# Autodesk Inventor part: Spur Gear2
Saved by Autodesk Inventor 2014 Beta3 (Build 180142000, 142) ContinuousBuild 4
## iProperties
Created: 2011-01
Part Number: Spur Gear2
Material: Steel
Document SubType Name: Modeling
Designer: Beta-8540w
Categories: <?xml version="1.0" encoding="UTF-16"?> <MemberInstance><Categories><FamilyTemplate><FamilyTemplateParameter ValueType="xs:double" Id="1" ObjectReferenceKey="da
Density: 1 g/cm^3
Appearance: Steel
CustomPartVersion: 1
Author: Beta-8540w
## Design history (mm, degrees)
sketch "Sketch1"
  geometry: C1 r 40.8 at (0, 0)
  constraints: 1 centre point
  dimensions: "d0" = 81.6 diameter of C1 (= da_da)
extrude "Extrusion1" new body sketch "Sketch1" distance "d1" = 13 (= da_b); taper "d2" = 0 deg
workplane "Work Plane2"
sketch "Sketch2"
  geometry: C1 r 40.8 at (0, 0) reference; C2 r 40 at (0, 0)
  constraints: 1 centre point, 1 coincident
  dimensions: "d3" = 80 diameter of C2 (= da_dw)
feature "Pitch Diameter" sketch "Sketch2" dims "d4" = 10, "d5" = 0
workplane "Work Plane8"
workplane "Work Plane9"
feature "Spur Gear" dims "da_b" = 13, "da_d" = 80, "da_aw" = 50, "da_da" = 81.6, "da_df" = 78, "da_dw" = 80, angle "da_beta" = 0 deg, "da_lefttooth" = 0, "da_righttooth" = 0
body "Solid1"
body "Srf1"
other parameters: "d17" = 0, "d34" = 0.31416 (computed from da_z), "d39" = 0, "d41" = 0, "d47" = 0, "d48" = 0
